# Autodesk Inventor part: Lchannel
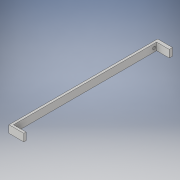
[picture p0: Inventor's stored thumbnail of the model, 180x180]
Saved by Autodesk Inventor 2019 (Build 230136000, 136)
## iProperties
Created: 2019-11
Part Number: Lchannel
Material: Generic
Document SubType Name: Sheet Metal
Designer: PRADYUMNA
Density: 1 g/cm^3
Sheet Metal Rule: Default_mm
Appearance: Default
Author: PRADYUMNA
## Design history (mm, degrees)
sketch "Sketch1"
  geometry: L1 (-5.488, 418.699)-(94.512, 418.699); L2 (94.512, 418.699)-(94.512, -581.301); L3 (94.512, -581.301)-(-5.488, -581.301); L4 (-5.488, -581.301)-(-5.488, 418.699); 1 further point
  constraints: 8 end point, 2 parallel, 1 horizontal, 1 perpendicular
  dimensions: "d0" = 1000 distance of L1.end L2.end; "d1" = 100 distance of L2.end L3.end
extrude "Extrusion1" new body sketch "Sketch1" distance "d2" = 50; taper "d3" = 0 deg
sketch "Sketch2"
  geometry: L1 (5.488, -418.699)-(5.488, 581.301) reference; L2 (5.488, -403.496)-(-79.218, -403.496); L3 (-79.218, -403.496)-(-79.218, 559.181); L4 (-79.218, 559.181)-(5.488, 559.181); L5 (5.488, 559.181)-(5.488, -403.496); 1 further point
  constraints: 8 end point, 2 parallel, 1 horizontal, 1 perpendicular, 1 point on line
extrude "Extrusion2" cut sketch "Sketch2" distance "d4" = 50; taper "d5" = 0 deg
sketch "Sketch3"
  geometry: C1 r 7.5 at (15.649, -25); 1 further point
  constraints: 1 centre point
  dimensions: "d6" = 15 diameter of C1
extrude "Extrusion3" cut sketch "Sketch3" distance "d7" = 50; taper "d8" = 0 deg
sketch "Sketch4"
  geometry: C1 r 10 at (945.331, -25); 1 further point
  constraints: 1 centre point
  dimensions: "d9" = 20 diameter of C1
extrude "Extrusion4" cut sketch "Sketch4" distance "d10" = 50; taper "d11" = 0 deg
thread "Thread1" dims "d12" = 10, "d13" = 0
thread "Thread2" dims "d14" = 10, "d15" = 0
sketch "Sketch5"
  geometry: 1 further point
sketch "Sketch6"
  geometry: C1 r 5 at (97.751, 25); C2 r 5 at (154.597, 25); C3 r 5 at (216.48, 25); C4 r 5 at (270.448, 25); C5 r 5 at (328.013, 25); C6 r 5 at (392.055, 25); C7 r 5 at (460.413, 25); C8 r 5 at (524.455, 25); C9 r 5 at (581.301, 25); C10 r 5 at (657.575, 25); C11 r 5 at (722.336, 25); C12 r 5 at (820.197, 25); C13 r 5 at (771.986, 25); C14 r 5 at (890.715, 25); 1 further point
  constraints: 14 centre point
  dimensions: "d16" = 10 diameter of C1; "d17" = 10 diameter of C2; "d18" = 10 diameter of C3; "d19" = 10 diameter of C4; "d20" = 10 diameter of C5; "d21" = 10 diameter of C6; "d22" = 10 diameter of C7; "d23" = 10 diameter of C8; "d24" = 10 diameter of C9; "d25" = 10 diameter of C10; "d26" = 10 diameter of C11; "d27" = 10 diameter of C12; "d28" = 10 diameter of C13; "d29" = 10 diameter of C14
extrude "Extrusion5" join sketch "Sketch6" distance "d30" = 10; taper "d31" = 0 deg
body "Solid1"
other parameters: "Thickness" = 0.5, "BendRadius" = 0.5 (= Thickness), "BendReliefWidth" = 0.5 (= Thickness), "BendReliefDepth" = 0.25 (= 0.5 x Thickness), "CornerReliefSize" = 2 (= 4 x Thickness), "SeamGap" = 0.01, "MinimumRemnant" = 1 (= 2 x Thickness), "TransitionRadius" = 0.5 (= BendRadius), "JacobiRadiusSize" = 0.5 (= BendRadius), "GapSize" = 0.5 (= Thickness)
